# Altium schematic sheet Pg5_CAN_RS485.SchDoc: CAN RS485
size 431 x 279 mm; Date: Not shown in title block; ApprovedBy: Not shown in title block; CheckedBy: Not shown in title block; Author: Not shown in title block; CompanyName: Not shown in title block; Engineer: Not shown in title block; Organization: Not shown in title block; Address1: Not shown in title block; Address2: Not shown in title block; Address3: Not shown in title block; Address4: Not shown in title block; DocumentNumber: 5; Revision: Use project parameter SCH_Rev; SheetNumber: 5; SheetTotal: 9; PageSetup: Record=PageOptions|CenterHorizontal=True|CenterVertical=True|PrintScale=1.00|XCorrection=1.00|YCorrection=1.00|PrintKind=0|BorderSize=5000000|LeftOffset=0|BottomOffset=0|Orientation=2|PaperLength=1000|PaperWidth=1000|Scale=100|PaperSource=15|PrintQuality=600|MediaType=1|DitherType=10|PaperKind=Letter|PrintScaleMode=1
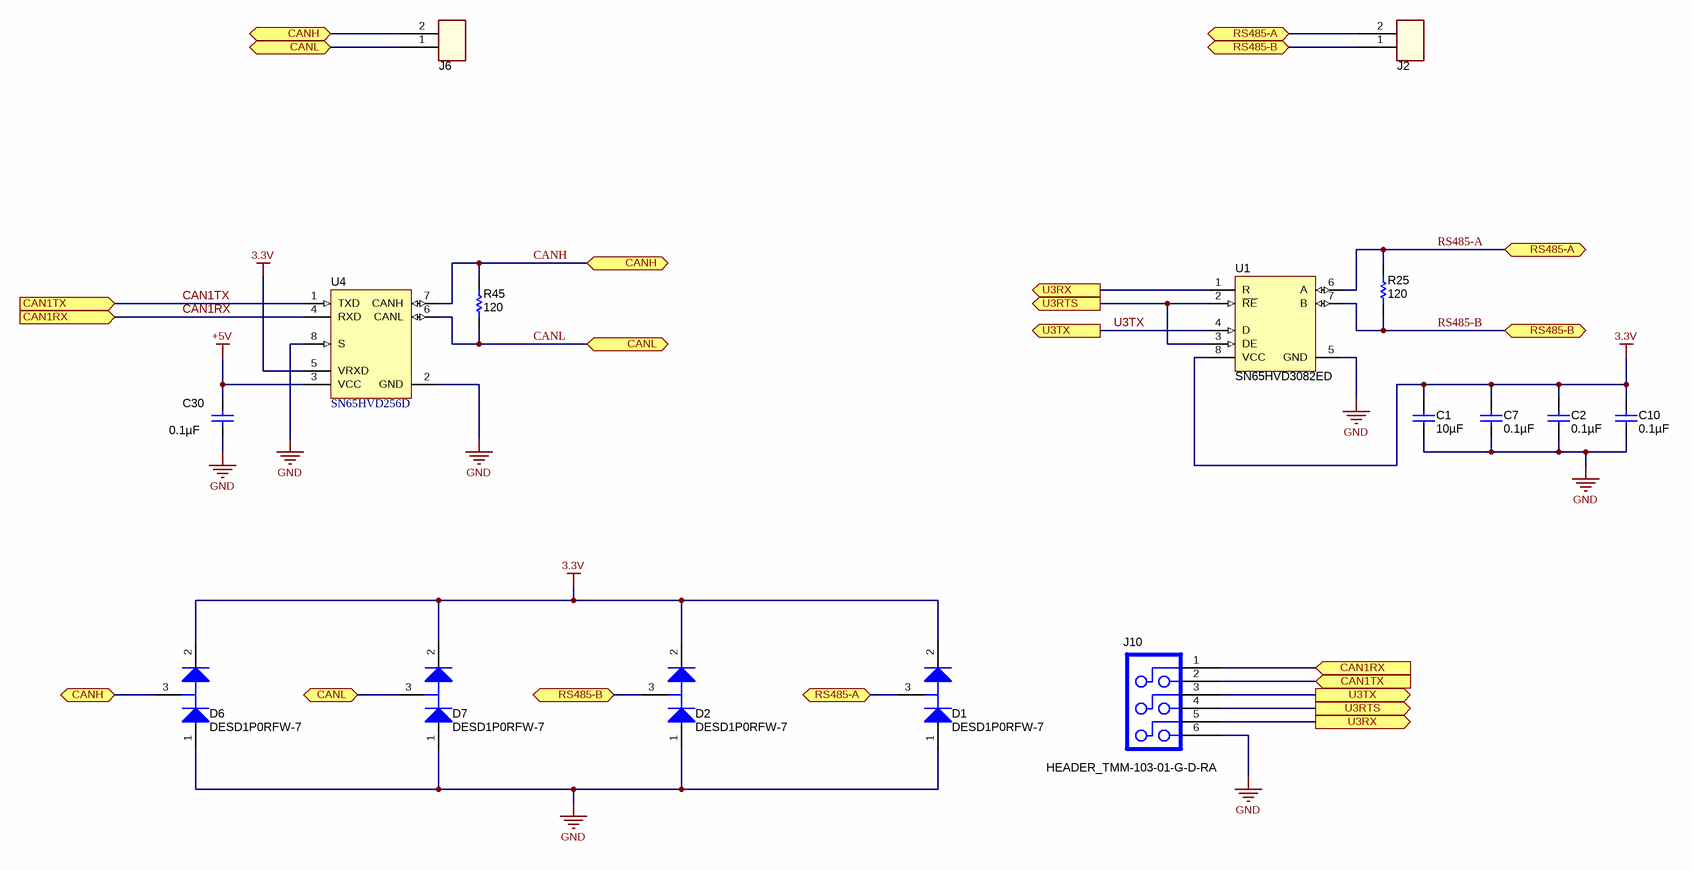
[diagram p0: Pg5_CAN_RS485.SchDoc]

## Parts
C1  ValueDisplayed: 10µF  [0603]  (hidden comment: C0603C106M9PACTU)
C2  ValueDisplayed: 0.1µF  [0603]  (hidden comment: GRM188R61C104KA01D)
C7  ValueDisplayed: 0.1µF  [0603]  (hidden comment: GRM188R61C104KA01D)
C10  ValueDisplayed: 0.1µF  [0603]  (hidden comment: GRM188R61C104KA01D)
C30  ValueDisplayed: 0.1µF  [0603]  (hidden comment: 06033C104JAT2A)
D1  DESD1P0RFW-7  [SOT-323]
D2  DESD1P0RFW-7  [SOT-323]
D6  DESD1P0RFW-7  [SOT-323]
D7  DESD1P0RFW-7  [SOT-323]
J2  CON-OSTVN02A150  [CN2_MTB_P100_PD80_D1.1_S5.54X6.5_STACK]  (value not drawn)
J6  CON-OSTVN02A150  [CN2_MTB_P100_PD80_D1.1_S5.54X6.5_STACK]  (value not drawn)
J10  HEADER_TMM-103-01-G-D-RA  [HEADER_TMM-103[2X]]
R25  value 120  [1206]  (hidden comment: RC1206FR-07120RL)
R45  value 120  [1206]  (hidden comment: RC1206FR-07120RL)
U1  SN65HVD3082ED  [D0008A_N]
U4  SN65HVD256D  [D0008A_L]

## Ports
CAN1RX (in), CAN1TX (in), CANH, CANL, RS485-A, RS485-B, U3RTS (out), U3RX (out), U3TX (out)

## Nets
3.3V: C1.1 C2.1 C7.1 C10.1 D1.2(K) D2.2(K) D6.2(K) D7.2(K) U1.8(VCC) U4.5(VRXD)
+5V: C30.2 U4.3(VCC)
GND: C1.2 C2.2 C7.2 C10.2 C30.1 D1.1(A) D2.1(A) D6.1(A) D7.1(A) J10.6 U1.5(GND) U4.2(GND) U4.8(S)
CAN1RX: J10.1 U4.4(RXD) ; port CAN1RX
CAN1TX: J10.2 U4.1(TXD) ; port CAN1TX
CANH: D6.3(C) J6.2 R45.2 U4.7(CANH) ; port CANH
CANL: D7.3(C) J6.1 R45.1 U4.6(CANL) ; port CANL
RS485-A: D1.3(C) J2.2 R25.2 U1.6(A) ; port RS485-A
RS485-B: D2.3(C) J2.1 R25.1 U1.7(B) ; port RS485-B
U3RTS: J10.4 U1.2(~{RE}) U1.3(DE) ; port U3RTS
U3RX: J10.5 U1.1(R) ; port U3RX
U3TX: J10.3 U1.4(D) ; port U3TX

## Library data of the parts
C1 = C0603C106M9PACTU: CAP, CERM, 10uF, 6.3V, +/-20%, X5R, 0603; Manufacturer: Kemet; Polarized: N; CompType: Capacitor; U/M: EA; Cap_F: 0.00001; Tolerance_%: 20; ESR_Ohm: 0.004; Value1: 0.004 ohm; VDC_V: 6.3; IRMS_A: 8.9; TaMin_C: -55; TaMax_C: 85
C2 C7 C10 = GRM188R61C104KA01D: CAP, CERM, 0.1uF, 16V, +/-10%, X5R, 0603; Manufacturer: MuRata; Polarized: N; CompType: Capacitor; U/M: EA; Cap_F: 0.0000001; Tolerance_%: 10; Value1: Unknown; VDC_V: 16; TaMin_C: -55; TaMax_C: 85
C30 = 06033C104JAT2A: CAP, CERM, 0.1uF, 25V, +/-5%, X7R, 0603; Manufacturer: AVX; Polarized: N; CompType: Capacitor; U/M: EA; Cap_F: 0.0000001; Tolerance_%: 5; ESR_Ohm: 0.05; Value1: 0.05 ohm; VDC_V: 25; TaMin_C: -55; TaMax_C: 125
D1 D2 D6 D7 = BAV99WT1G: Diode, P-N, 70V, 0.2A, SOT-323; Manufacturer: Diodes Inc
J2 J6 = CON-OSTVN02A150: Terminal Block, 4x1, 2.54mm, TH; Manufacturer: On Shore Technology Inc; SymbolCreator: x0120606
J10 = HEADER_TMM-103-01-G-D-RA: Header, 2mm, Low Profile 2x3; Manufacturer: Samtec; Area: 57.75 mm
R25 R45 = RC1206FR-07120RL: RES, 120 ohm, 1%, 0.25W, 1206; Manufacturer: Yageo America; CompType: Resistor; Value_Code: 120R; Tolerance_%: 1; Power_W: 0.25; VDC_V: 200; TempCo: 100 ppm/C; U/M: EA
U1 = SN65HVD3082ED: IC, RS485 TRANSCEIVER LP, 8-SOIC; Manufacturer: TEXAS INSTRUMENTS; CompType: LOW-POWER RS-485 TRANSCEIVER; SymbolCreator: x0199378
U4 = SN65HVD256D: CAN Transceiver with Fast Loop Times for Highly Loaded Networks, 85 mA, 5 V, -40 to 125 degC, 8-pin SOIC (D), Green (RoHS & no Sb/Br); Manufacturer: Texas Instruments; Alternate Manufacturer: None; Alternate PartNumber: Equivalent; Drivers Per Package: 1; Bus Fault Voltage(V): -27 to 40; ICC(Max)(mA): 85; Supply Voltage(s)(V): 5; Rating: Catalog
